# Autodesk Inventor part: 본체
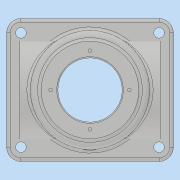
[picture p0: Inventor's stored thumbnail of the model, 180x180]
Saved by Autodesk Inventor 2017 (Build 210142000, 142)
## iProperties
Part Number: 본체
Material: 일반
Document SubType Name: Modeling
Designer: MRC
Density: 1 g/cm^3
Appearance: 기본값
Author: MRC
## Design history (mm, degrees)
sketch "스케치1"
  geometry: C1 r 50 at (0, 0); 1 further point
  constraints: 1 centre point, 1 coincident
  dimensions: "d0" = 100 diameter of C1
extrude "돌출1" new body sketch "스케치1" stored distance "d1" = 120; taper "d2" = 0 deg
sketch "스케치5"
  geometry: C1 r 50 at (0, 0) reference; C2 r 41 at (0, 0)
  constraints: 1 centre point, 1 coincident
  dimensions: "d17" = 82 diameter of C2
extrude "돌출4" join sketch "스케치5" distance "d18" = 5; taper "d19" = 0 deg
sketch "스케치6"
  geometry: L1 (70, -60)-(-70, -60); L2 (-70, -60)-(-70, 60); L3 (-70, 60)-(70, 60); L4 (70, 60)-(70, -60); L5 (70, -60)-(-70, 60); L6 (-70, -60)-(70, 60); 1 further point
  constraints: 12 end point, 2 midpoint, 2 parallel, 1 horizontal, 1 perpendicular
  dimensions: "d20" = 140 distance of L2.end L3.end; "d21" = 120 distance of L1.end L2.end
extrude "돌출5" join sketch "스케치6" distance "d22" = 10; taper "d23" = 0 deg
node "작업 평면1"
sketch "스케치7"
  geometry: C1 r 41 at (0, 0); 1 further point
  constraints: 1 centre point, 1 coincident
  dimensions: "d25" = 82 diameter of C1
extrude "돌출6" join sketch "스케치7" stored distance "d26" = 10; taper "d27" = 0 deg
sketch "스케치8"
  geometry: 2 further points
  constraints: 1 coincident
hole "구멍2" sketch "스케치8" at (0, 0) diameter "d28" = 54; stored, may be unused: countersink angle "d32" = 90 deg, drill point angle "d34" = 0 deg; dims "d29" = 6, "d30" = 84, "d31" = 112, "d33" = 8
sketch "스케치9"
  geometry: C1 r 27 at (0, 0); 1 further point
  constraints: 1 centre point, 1 coincident
  dimensions: "d35" = 54 diameter of C1
extrude "돌출7" cut sketch "스케치9" stored distance "d36" = 10; taper "d37" = 0 deg
sketch "스케치10"
  geometry: 2 further points
  constraints: 1 vertical alignment
  dimensions: "d38" = 33 distance of point (0, 0) point (0, 33)
hole "구멍3" sketch "스케치10" at (0, 33) diameter "d39" = 3.242; stored, may be unused: countersink angle "d43" = 90 deg, drill point angle "d45" = 0 deg; dims "d40" = 8, "d41" = 84, "d42" = 112, "d44" = 10
sketch "스케치11"
  geometry: 2 further points
  constraints: 1 vertical alignment
  dimensions: "d46" = 33 distance of point (0, 0) point (0, 33)
hole "구멍4" sketch "스케치11" at (0, 33) diameter "d47" = 3.242; stored, may be unused: countersink angle "d51" = 90 deg, drill point angle "d53" = 0 deg; dims "d48" = 8, "d49" = 84, "d50" = 112, "d52" = 10
fillet "모깎기1" dims "d60" = 12
fillet "모깎기2" dims "d61" = 3
fillet "모깎기3" dims "d62" = 6
fillet "모깎기4" dims "d63" = 3
fillet "모깎기5" dims "d64" = 3
sketch "스케치12"
  geometry: C1 r 4.5 at (-58, 48); A1 r 12 centre (-58, 48) between (-58, 60) and (-70, 48) reference; 1 further point
  constraints: 1 centre point, 1 concentric
  dimensions: "d65" = 9 diameter of C1
extrude "돌출8" cut sketch "스케치12" stored distance "d66" = 10; taper "d67" = 0 deg
node "작업 평면2"
sketch "스케치13"
  geometry: L1 (-58, -60)-(58, -60) reference; 2 further points
  constraints: 1 vertical alignment, 1 other
  dimensions: "d69" = 66 distance from line of point (0, 6) L1
feature "엠보싱1" sketch "스케치13" dims "d25" = 82, "d70" = 0.5, "d71" = 0
chamfer "모따기1" distance "d72" = 1; stored, may be unused: second distance "d73" = 2, angle "d74" = 45 deg
node "솔리드1"
pattern_circular "원형 패턴1" dims angle "d55" = 360 deg
pattern_circular "원형 패턴2" dims angle "d58" = 360 deg
mirror "미러1"
mirror "미러2"
mirror "미러3"
other parameters: "d24" = 59
